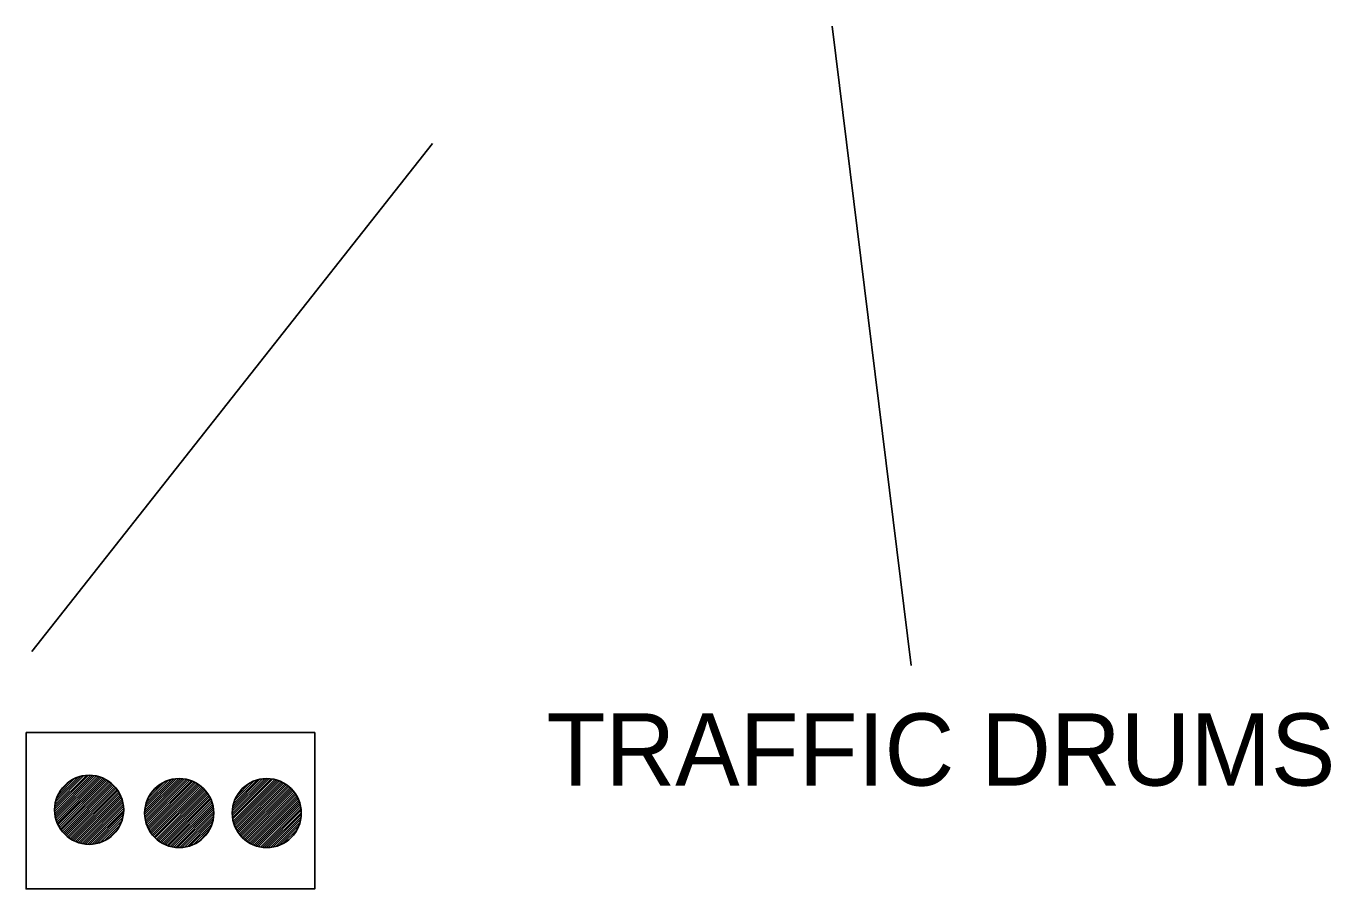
# Model space of a CAD drawing. Extents: x 1398460 to 1408037, y 380768 to 383968.
# Drawn here: x 1401032 to 1401140.4, y 380988.7 to 381060.3 of the extents above; entities that cross this region are included whole.
import ezdxf

# ---------------------------------------------------------------- set-up
doc = ezdxf.new("R2010")
doc.units = 0
for name, color, linetype in [('Default', 7, 'Continuous'), ('R_Border', 7, 'Continuous'), ('R_Dimension', 7, 'Continuous'), ('R_MOT', 7, 'Continuous')]:
    doc.layers.add(name, color=color, linetype=linetype)

msp = doc.modelspace()

# ---------------------------------------------------------------- linework, layer by layer
at = {"layer": 'Default'}
for p, q in [((1401037.39, 380998.11), (1401034.38, 380995.1)), ((1401037.21, 380998.11), (1401034.38, 380995.28)), ((1401037.03, 380998.1), (1401034.39, 380995.46)), ((1401037.55, 380998.1), (1401034.4, 380994.94)), ((1401036.83, 380998.08), (1401034.41, 380995.66)), ((1401037.71, 380998.08), (1401034.42, 380994.78)), ((1401037.86, 380998.05), (1401034.45, 380994.63)), ((1401036.61, 380998.04), (1401034.45, 380995.88)), ((1401038, 380998.01), (1401034.48, 380994.49)), ((1401038.14, 380997.97), (1401034.52, 380994.36)), ((1401036.37, 380997.97), (1401034.52, 380996.13)), ((1401038.27, 380997.93), (1401034.57, 380994.22)), ((1401038.39, 380997.88), (1401034.62, 380994.1)), ((1401036.08, 380997.86), (1401034.63, 380996.41)), ((1401038.52, 380997.82), (1401034.67, 380993.98)), ((1401038.63, 380997.76), (1401034.73, 380993.86)), ((1401044.7, 380997.85), (1401041.87, 380995.01)), ((1401044.87, 380997.84), (1401041.87, 380994.84)), ((1401044.51, 380997.84), (1401041.88, 380995.2)), ((1401045.04, 380997.83), (1401041.88, 380994.68)), ((1401044.31, 380997.82), (1401041.9, 380995.4)), ((1401045.19, 380997.81), (1401041.9, 380994.52)), ((1401045.34, 380997.78), (1401041.93, 380994.37)), ((1401044.1, 380997.77), (1401041.94, 380995.62)), ((1401045.49, 380997.75), (1401041.96, 380994.23)), ((1401052.05, 380997.85), (1401049.14, 380994.94)), ((1401052.22, 380997.84), (1401049.14, 380994.77)), ((1401051.87, 380997.84), (1401049.14, 380995.12)), ((1401051.68, 380997.83), (1401049.16, 380995.31)), ((1401052.38, 380997.82), (1401049.16, 380994.61)), ((1401052.53, 380997.8), (1401049.18, 380994.45)), ((1401051.47, 380997.8), (1401049.19, 380995.52)), ((1401052.68, 380997.77), (1401049.21, 380994.31)), ((1401051.23, 380997.74), (1401049.24, 380995.75)), ((1401052.82, 380997.73), (1401049.25, 380994.17)), ((1401038.74, 380997.7), (1401034.8, 380993.75)), ((1401035.69, 380997.65), (1401034.85, 380996.8)), ((1401038.85, 380997.63), (1401034.87, 380993.64)), ((1401038.96, 380997.55), (1401034.94, 380993.54)), ((1401039.06, 380997.48), (1401035.02, 380993.44)), ((1401039.15, 380997.4), (1401035.1, 380993.34)), ((1401039.24, 380997.31), (1401035.18, 380993.25)), ((1401039.33, 380997.22), (1401035.27, 380993.16)), ((1401039.42, 380997.13), (1401035.36, 380993.07)), ((1401039.5, 380997.04), (1401035.46, 380992.99)), ((1401039.58, 380996.94), (1401035.56, 380992.92)), ((1401039.65, 380996.83), (1401035.66, 380992.84)), ((1401039.72, 380996.72), (1401035.77, 380992.78)), ((1401045.62, 380997.71), (1401042.01, 380994.09)), ((1401043.85, 380997.71), (1401042.01, 380995.86)), ((1401045.75, 380997.66), (1401042.05, 380993.96)), ((1401045.88, 380997.61), (1401042.1, 380993.83)), ((1401043.56, 380997.6), (1401042.12, 380996.15)), ((1401046, 380997.56), (1401042.16, 380993.71)), ((1401046.12, 380997.5), (1401042.22, 380993.6)), ((1401046.23, 380997.43), (1401042.28, 380993.48)), ((1401043.18, 380997.38), (1401042.33, 380996.54)), ((1401046.34, 380997.36), (1401042.35, 380993.38)), ((1401046.44, 380997.29), (1401042.42, 380993.27)), ((1401046.54, 380997.21), (1401042.5, 380993.17)), ((1401046.64, 380997.13), (1401042.58, 380993.08)), ((1401046.73, 380997.05), (1401042.67, 380992.98)), ((1401046.82, 380996.96), (1401042.75, 380992.9)), ((1401046.9, 380996.87), (1401042.85, 380992.81)), ((1401046.98, 380996.77), (1401042.94, 380992.73)), ((1401047.06, 380996.67), (1401043.04, 380992.65)), ((1401052.95, 380997.69), (1401049.29, 380994.03)), ((1401050.97, 380997.65), (1401049.33, 380996.02)), ((1401053.08, 380997.64), (1401049.34, 380993.9)), ((1401053.2, 380997.59), (1401049.4, 380993.78)), ((1401053.32, 380997.53), (1401049.45, 380993.66)), ((1401050.64, 380997.5), (1401049.49, 380996.35)), ((1401053.44, 380997.47), (1401049.52, 380993.55)), ((1401053.55, 380997.4), (1401049.58, 380993.44)), ((1401053.65, 380997.33), (1401049.65, 380993.33)), ((1401053.76, 380997.26), (1401049.73, 380993.23)), ((1401053.85, 380997.18), (1401049.81, 380993.13)), ((1401053.95, 380997.1), (1401049.89, 380993.04)), ((1401054.04, 380997.01), (1401049.97, 380992.94)), ((1401054.13, 380996.92), (1401050.06, 380992.86)), ((1401054.21, 380996.83), (1401050.16, 380992.78)), ((1401054.29, 380996.73), (1401050.26, 380992.7)), ((1401039.78, 380996.61), (1401035.88, 380992.71)), ((1401039.84, 380996.49), (1401036, 380992.65)), ((1401039.9, 380996.37), (1401036.12, 380992.6)), ((1401039.95, 380996.25), (1401036.25, 380992.55)), ((1401039.99, 380996.12), (1401036.38, 380992.5)), ((1401040.03, 380995.98), (1401036.51, 380992.46)), ((1401040.07, 380995.84), (1401036.66, 380992.42)), ((1401040.1, 380995.69), (1401036.8, 380992.4)), ((1401047.13, 380996.57), (1401043.15, 380992.58)), ((1401047.2, 380996.46), (1401043.25, 380992.51)), ((1401047.27, 380996.35), (1401043.37, 380992.45)), ((1401047.33, 380996.23), (1401043.48, 380992.39)), ((1401047.38, 380996.11), (1401043.6, 380992.33)), ((1401047.43, 380995.98), (1401043.73, 380992.28)), ((1401047.48, 380995.85), (1401043.86, 380992.24)), ((1401047.52, 380995.72), (1401044, 380992.2)), ((1401047.55, 380995.57), (1401044.14, 380992.16)), ((1401054.36, 380996.63), (1401050.36, 380992.62)), ((1401054.43, 380996.52), (1401050.46, 380992.55)), ((1401054.5, 380996.41), (1401050.57, 380992.48)), ((1401054.56, 380996.3), (1401050.69, 380992.42)), ((1401054.62, 380996.18), (1401050.81, 380992.36)), ((1401054.72, 380995.93), (1401051.06, 380992.26)), ((1401054.77, 380995.79), (1401051.19, 380992.22)), ((1401054.8, 380995.65), (1401051.33, 380992.18)), ((1401040.12, 380995.53), (1401036.96, 380992.38)), ((1401040.13, 380995.37), (1401037.13, 380992.36)), ((1401040.13, 380995.19), (1401037.3, 380992.36)), ((1401040.12, 380995.01), (1401037.49, 380992.37)), ((1401040.1, 380994.81), (1401037.68, 380992.39)), ((1401040.06, 380994.59), (1401037.9, 380992.44)), ((1401047.58, 380995.42), (1401044.29, 380992.13)), ((1401047.6, 380995.27), (1401044.45, 380992.11)), ((1401047.61, 380995.1), (1401044.61, 380992.1)), ((1401047.62, 380994.93), (1401044.78, 380992.1)), ((1401047.61, 380994.74), (1401044.97, 380992.11)), ((1401047.58, 380994.54), (1401045.17, 380992.13)), ((1401054.84, 380995.51), (1401051.48, 380992.15)), ((1401054.86, 380995.36), (1401051.63, 380992.12)), ((1401054.88, 380995.2), (1401051.79, 380992.11)), ((1401054.89, 380995.03), (1401051.96, 380992.1)), ((1401054.88, 380994.85), (1401052.14, 380992.1)), ((1401054.87, 380994.66), (1401052.33, 380992.12)), ((1401039.99, 380994.34), (1401038.15, 380992.5)), ((1401039.88, 380994.06), (1401038.44, 380992.61)), ((1401039.66, 380993.67), (1401038.83, 380992.83)), ((1401047.54, 380994.33), (1401045.39, 380992.17)), ((1401047.47, 380994.08), (1401045.63, 380992.24)), ((1401047.36, 380993.79), (1401045.92, 380992.35)), ((1401047.15, 380993.4), (1401046.31, 380992.56)), ((1401054.84, 380994.45), (1401052.53, 380992.15)), ((1401054.79, 380994.22), (1401052.76, 380992.2)), ((1401054.7, 380993.96), (1401053.02, 380992.28)), ((1401054.56, 380993.64), (1401053.34, 380992.43)), ((1401054.18, 380993.08), (1401053.9, 380992.81))]:
    msp.add_line(p, q, dxfattribs=at)
msp.add_lwpolyline([(1401032.03, 381001.66), (1401032.03, 380988.67), (1401056, 380988.67), (1401056, 381001.66)], close=True, dxfattribs=at)
for centre in [(1401037.26, 380995.24), (1401044.74, 380994.97), (1401052.01, 380994.97)]:
    msp.add_circle(centre, 2.87, dxfattribs=at)
at = {"layer": 'R_Dimension'}
msp.add_line((1401098.97, 381060.32), (1401105.52, 381007.23), dxfattribs=at)
at = {"layer": 'R_MOT'}
for p, q in [((1401032.51, 381008.38), (1401065.77, 381050.57)), ((1401050.93, 380992.31), (1401054.68, 380996.05))]:
    msp.add_line(p, q, dxfattribs=at)

# ---------------------------------------------------------------- texts
at = {"layer": 'R_Border'}
msp.add_text('TRAFFIC DRUMS', height=6, dxfattribs=at).set_placement((1401075.24, 380997.25))

doc.saveas('drawing.dxf')
